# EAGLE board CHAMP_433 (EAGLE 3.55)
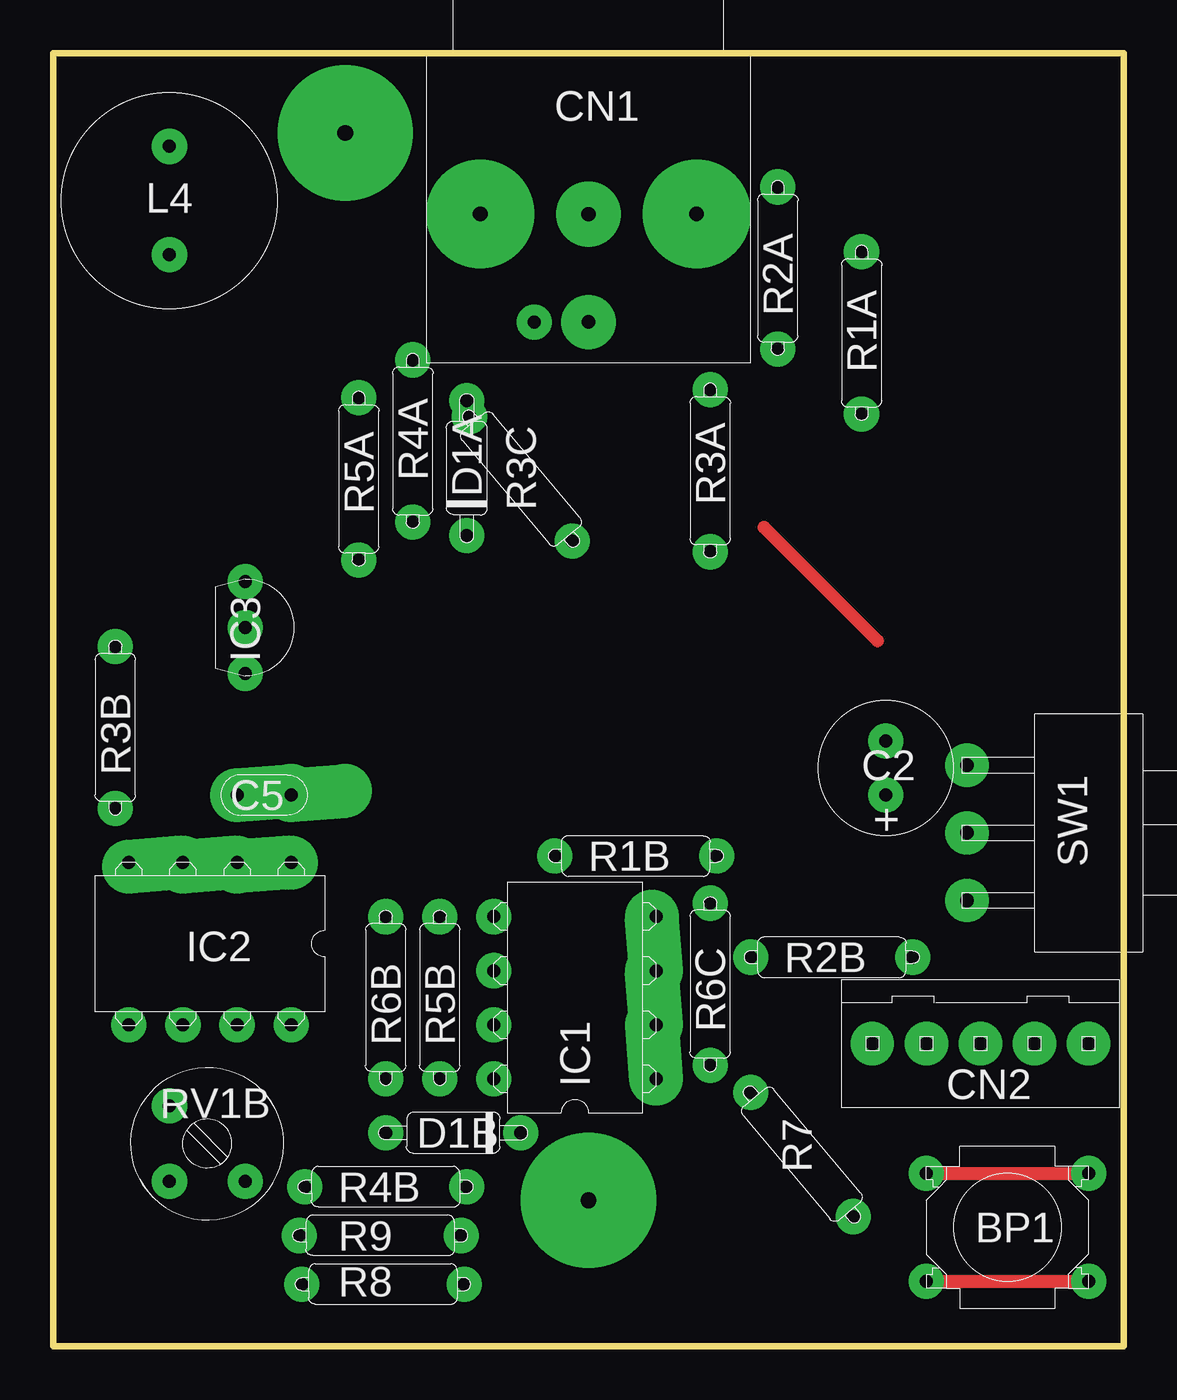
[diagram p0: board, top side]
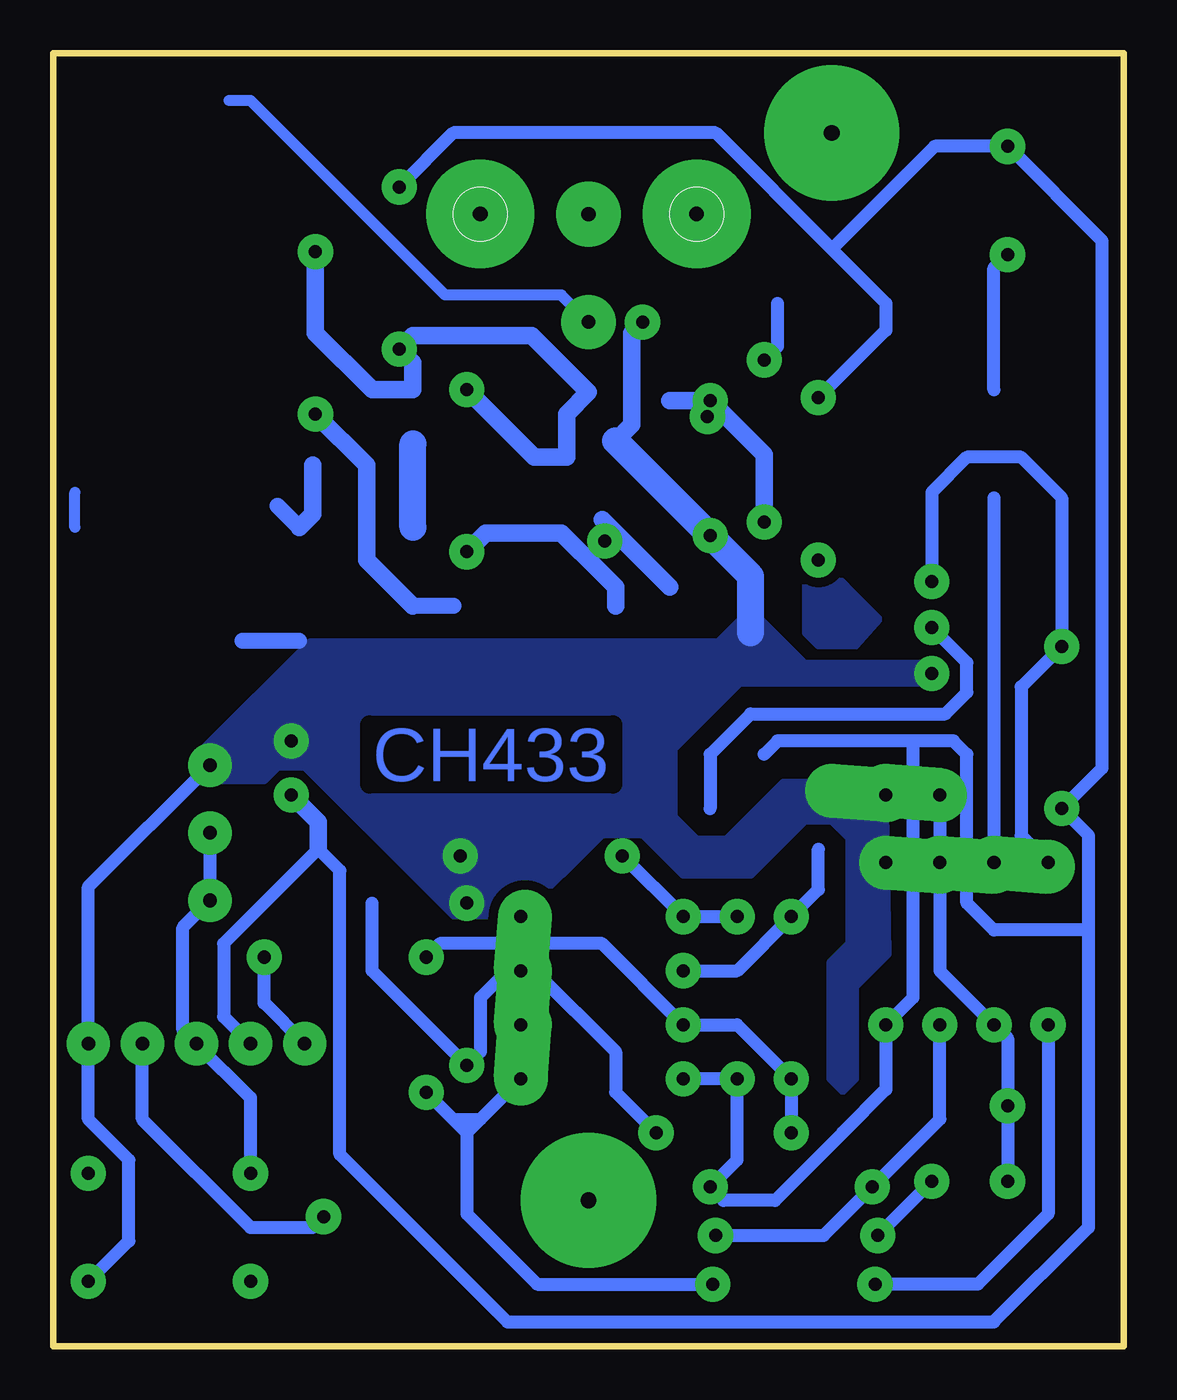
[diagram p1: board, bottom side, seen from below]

Size 50.29 x 60.77 mm. Coordinates in mm from the lower left corner, seen from the top.
Outline: 50.29,0 50.29,60.77 0,60.77 0,0 50.29,0
Copper layers used: COTE_COM, COTE_SOU
EXCL_SOU: area 24,26.4 to 35.4,29.2

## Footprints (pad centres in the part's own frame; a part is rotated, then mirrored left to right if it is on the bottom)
-MICRO = drill 0.612 pad 1.651 round:  -3.81,-2.54;  -3.81,2.54;  3.81,2.54;  3.81,-2.54
IM-6-0 = drill 0.612 pad 1.651 round:  -1.27,0;  1.27,0
2,5-1 = drill 0.612 pad 2.54 offset:  -1.27,0;  1.27,0
C-L = drill 0.691 pad 5.08 round:  5.08,0;  -5.08,0 | drill 0.637 pad 2.54 round:  0,5.08 | drill 0.612 pad 1.651 round:  2.54,5.08
14C05V = drill 0.637 pad 2.032 round:  -5.08,0;  -2.54,0;  0,0;  2.54,0;  5.08,0
6,3 = drill 0.612 pad 1.651 round:  3.175,0;  -3.175,0
-3,0MM = drill 0.744 pad 6.35 round:  0,0
L-08 = drill 0.612 pad 2.54 offset:  0,0;  2.54,0;  5.08,0 | drill 0.612 pad 1.651 round:  7.62,0;  7.62,7.62;  5.08,7.62;  2.54,7.62;  0,7.62
 = drill 0.612 pad 1.651 round:  2.159,0;  -2.159,0;  0,0
470MH = drill 0.612 pad 1.651 round:  -2.54,0;  2.54,0
10-7S = drill 0.612 pad 1.651 round:  -3.81,0;  3.81,0
ø0#R-1 = drill 0.612 pad 1.651 round:  -2.921,-2.413;  2.921,2.413
1T-45 = drill 0.612 pad 1.651 round:  -1.778,-1.778;  -1.778,1.778;  1.778,1.778
-GLIS = drill 0.637 pad 2.032 round:  0,3.175;  0,0;  0,-3.175

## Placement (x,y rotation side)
BP1  ON  [-MICRO]  44.83,5.59 0 top
BUZZER  PIEZO  [-PI13V]  6.1,42.42 270 top
C1A  104  [2,5-0]  13.21,11.3 90 top
C1B  104  [2,5-0]  36.58,23.37 180 top
C1C  104  [2,5-0]  34.04,20.83 180 top
C1D  104  [2,5-0]  33.4,43.69 270 top
C1E  104  [2,5-60]  24.51,43.69 90 top
C2  100æ  [IM-6-0]  39.12,27.18 90 top
C3  2p2  [2,5-0]  36.83,41.4 180 top
C4A  47p  [2,5-0]  24.51,37.59 90 top
C4B  47p  [2,5-0]  12.07,32.89 270 top
C5  10n  [2,5-1]  9.91,25.91 0 top
CN1  BNC  [C-L]  25.15,53.21 180 top
CN2  S +9- +G-  [14C05V]  43.56,14.22 0 top
CV1  1/6p  [VA-P34]  36.07,35.81 90 top
D1A  914  [6,3]  19.43,41.27 90 top
D1B  914  [6,3]  18.8,10.03 180 top
F1  FIXATION  [-3,0MM]  25.15,6.86 0 top
F2  FIXATION  [-3,0MM]  13.72,57.02 0 top
IC1  TLC272  [L-08]  28.32,12.57 90 top
IC1_SCH  TLC272  [082]  27.69,12.57 180 top
IC2  TLC555  [L-08]  11.18,22.73 180 top
IC2_SCH  TLC555  [5]  11.18,22.1 270 top
IC3  MC34064  []  9.02,33.78 270 top
L1  115mm  [433-A1]  45.09,48.89 0 top
L2  45nH  [433-13]  44.58,36.96 0 top
L3  4T/2,5  [4T-2,5]  27.43,40 0 top
L4  470mH  [470MH]  5.46,53.85 90 top
R1A  100K  [10-7S]  37.97,47.62 270 top
R1B  100K  [10-7S]  27.37,23.05 0 top
R2A  220R  [10-7S]  34.04,50.67 270 top
R2B  220R  [10-7S]  36.58,18.29 0 top
R3A  4K7  [10-7S]  30.86,41.15 270 top
R3B  4K7  [10-7S]  2.92,29.08 90 top
R3C  4K7  [ø0#R-1]  21.97,40.77 270 top
R4A  1K  [10-7S]  16.89,42.55 270 top
R4B  1K  [10-7S]  15.62,7.49 180 top
R5A  220K  [10-7S]  14.35,40.77 270 top
R5B  220K  [10-7S]  18.16,16.38 90 top
R6A  1M  [10]  14.35,28.45 270 top
R6B  1M  [10-7S]  15.62,16.38 90 top
R6C  1M  [10-7S]  30.86,17.02 90 top
R7  33K  [ø0#R-1]  35.18,9.02 90 top
R8  10K  [10-7S]  15.49,2.92 180 top
R9  33K  [10-7S]  15.37,5.21 180 top
RV1A  22K  [1T-00]  13.72,49.02 0 top
RV1B  22K  [1T-45]  7.24,9.52 90 top
RV1C  22K  [1T-00]  19.43,27.81 180 top
SW1  ON/OFF  [-GLIS]  42.93,24.13 0 top
T1A  BFR91  [BFR91I]  27.69,34.8 0 top
T1B  BFR91  [BFR91I]  17.53,35.69 0 top
U$6  [TRE-55]  13.72,57.02 0 top
U$24  [TRE-55]  25.15,6.86 0 top

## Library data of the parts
BP1 BUZZER D1A D1B F1 F2 IC3 L1-L4 R1A R1B R2A R2B R3A R3B R4A R4B R5A R5B R6A R6B R6C R8 R9 RV1A RV1B RV1C SW1 T1A T1B U$6 U$24 = EAGLE
C1A C1B C1C C1D C1E C2 C3 C4A C4B C5 CV1 = CONDO
CN1 = CONNEC
CN2 = CONN-HE
IC1 IC2 = INTEL
IC1_SCH IC2_SCH = SCHEMA
R3C R7 = RESISTAN

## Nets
0V: BP1. C1A. C1B. C1C. C1D. C1E. C2. C4B. C5. CN1. CN2. CV1. D1A. IC1. IC2. IC3. L2. R1B. R6C. RV1C. SW1. T1A. T1B.
0V_PILE: BP1. CN2. SW1.
3_+REPOS: BUZZER. IC2.
4V6_MINI: IC3. RV1C.
6-2_RC: C5. IC2. RV1B.
7: IC2. R4B. R9.
+9V: C1A. C1B. C2. CN2. IC1. IC2. L4. R2A. R3B. R4B. R5A. R5B. RV1A. RV1C.
+9V_FILT: C1D. C1E. L3. R1A. R2A. R3A.
+GALVANO: CN2. R7.
ANTENNE: CN1. L1.
B_T1A: C3. R1A. T1A.
B_T1B: C4A. R3C. T1B.
C_T1A: C4A. L3. R3A. T1A.
C_T1B: C4B. R5A. R6A. T1B.
E1+_TEMP: C1C. D1B. IC1. R6C.
E2+_+2V8: IC1. R1B. R5B.
E2-_IN: IC1. R6A. R6B.
F_MINI: R9. RV1B.
LC_433: C3. CV1. L2.
LCWý=1: BUZZER. L4.
MIL: L1. L2.
MIN: R4A. RV1A.
OSCILLO: CN2. R2B.
RST_555: IC2. IC3. R3B.
S1_+: IC1. R7. R8.
S2_+: D1B. IC1. R2B. R6B.
VCO_555: IC2. R8.
Z: D1A. R3C. R4A.

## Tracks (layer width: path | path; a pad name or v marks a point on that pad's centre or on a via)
0V
  COTE_COM 0.61: 41.02,3.05 BP1. | 33.4,38.48 38.73,33.15
  COTE_SOU 0.61: 42.93,27.3 48.64,21.59 CN2. 48.64,10.67 46.74,8.76 46.74,4.95 BP1.
  COTE_SOU 0.762: 38.73,33.15 41.4,33.15
  COTE_SOU 0.813: 23.88,42.55 23.11,43.31 23.11,47.62 CN1.
  COTE_SOU 1.27: 23.88,42.55 D1A. 17.53,36.2 17.53,33.53 | 33.4,38.48 33.4,42.42
  pour COTE_SOU (isolate 0.444, no thermals): 11.18,26.54 11.05,18.41 12.57,16.89 12.57,12.57 13.21,11.94 13.84,12.57 13.84,18.03 12.95,18.92 12.95,26.54
  pour COTE_SOU (isolate 0.444, no thermals): 11.18,26.54 16,26.54 18.67,23.88 20.07,23.88 21.08,24.89 21.08,28.07 18.03,31.12 8.89,31.12 8.38,31.62 8.89,32.13 14.99,32.13 17.53,34.67 19.05,33.15 38.23,33.15 43.31,28.07 43.31,26.54 40.39,26.54 39.75,27.18 38.48,27.18 31.5,20.19 28.32,20.19 24.51,24 22.61,24 20.7,22.1 17.53,22.1 14.99,24.64 13.72,24.64 12.83,23.75 11.18,23.75
0V_PILE
  COTE_COM 0.61: 41.02,8.13 48.64,8.13
  COTE_SOU 0.61: 42.93,24.13 SW1. 44.2,19.68 44.2,14.86 43.56,14.22 41.02,11.68 41.02,8.13
3_+REPOS
  COTE_SOU 0.61: 6.1,39.88 6.1,22.73
4V6_MINI
  COTE_SOU 0.61: 19.43,25.27 19.43,27.81 17.53,29.72 8.38,29.72 7.37,30.73 7.37,32.13 IC3.
6-2_RC
  COTE_SOU 0.61: 8.64,25.91 8.64,22.73 8.64,17.65 6.1,15.11 5.46,14.48 RV1B. 5.46,7.75
7
  COTE_SOU 0.61: 8.64,15.11 8.64,10.67 R4B. 14.1,5.21 19.18,5.21
+9V
  COTE_SOU 0.61: 13.72,51.56 11.18,49.02 11.18,47.75 14.35,44.58 | IC1. 18.16,12.57 18.16,8.76 19.43,7.49 18.8,6.86 16.38,6.86 13.21,10.03 11.18,12.06 IC2. 9.91,16.38 9.91,28.45 | 9.91,28.45 8,28.45 7.37,27.81 7.37,20.83 6.1,19.56 1.65,19.56 | 1.65,19.56 1.65,5.59 6.1,1.14 28.96,1.14 36.83,9.02 36.83,22.35 37.85,23.37 42.29,18.92 42.29,15.49 41.02,14.22 | 1.65,19.56 1.65,24 2.92,25.27 1.02,27.18 1.02,51.94 L4. 8.89,56.39 13.72,51.56 | 9.91,28.45 16.26,28.45 16.89,27.81 | 13.72,51.56 19.18,57.02 31.5,57.02 34.04,54.48
  COTE_SOU 0.813: 37.85,23.37 37.85,24.64 39.12,25.91
+9V_FILT
  COTE_SOU 0.813: 37.97,51.44 37.97,47.62 35.31,44.96 33.4,44.96 33.4,46.23 R2A. 33.4,47.5 27.81,47.5 25.15,44.83 26.16,43.81 26.16,41.78 27.69,41.78 30.86,44.96
+GALVANO
  COTE_SOU 0.61: 46.1,14.22 46.1,10.67 41.02,5.59 38.1,5.59 37.59,6.1
ANTENNE
  COTE_SOU 0.508: 25.15,48.13 26.42,49.4 31.88,49.4 41.02,58.55 42.04,58.55
B_T1A
  COTE_SOU 0.762: 31.5,34.8 33.4,34.8
  COTE_SOU 0.813: 33.4,34.8 35.56,36.96 35.56,41.4 R1A.
B_T1B
  COTE_SOU 0.813: 21.34,35.69 22.61,36.96 24.51,38.86
C_T1A
  COTE_SOU 0.813: 23.88,34.8 23.88,35.69 24.51,36.32 26.42,38.23 28.7,38.23 29.97,38.23 R3A.
C_T1B
  pour COTE_SOU (isolate 0.444, no thermals): 14.99,33.53 14.99,36.7 14.48,37.21 11.43,34.16 12.57,32.89 14.35,32.89
E1+_TEMP
  COTE_SOU 0.61: 35.31,20.83 35.31,17.65 30.86,13.21 30.23,13.84 30.23,15.75 30.23,16.38 28.96,17.65 28.32,17.65 27.69,17.65 23.88,13.84 23.88,11.94 D1B.
E2+_+2V8
  COTE_SOU 0.61: R5B. 20.7,20.19 23.56,23.05
E2-_IN
  COTE_SOU 0.61: 20.7,17.65 18.16,17.65 R6B. 14.35,21.46 14.35,23.37
F_MINI
  COTE_SOU 0.61: R9. 9.02,7.75
LC_433
  COTE_SOU 0.762: 38.73,38.48 39.75,39.5
  COTE_SOU 0.813: 38.1,41.4 38.1,39.12 38.73,38.48
LCWý=1
  COTE_SOU 0.61: 6.1,44.96 6.1,50.67 5.46,51.31
MIL
  COTE_SOU 0.508: 49.28,38.48 49.28,40.13
MIN
  COTE_SOU 0.61: 16.26,49.02 16.26,46.99 16.89,46.36
N$1  (via drill 0.66 pad 3.05)
  other vias: 25.15,53.21
OSCILLO
  COTE_SOU 0.61: 38.48,14.22 40.39,16.13 R2B.
RST_555
  COTE_SOU 0.61: 3.56,22.73 4.83,24 4.83,30.99 R3B. 2.92,39.88 4.83,41.78 7.37,41.78 9.02,40.13 9.02,35.94
S1_+
  COTE_SOU 0.61: 28.32,15.11 28.32,12.57 30.23,10.67 | 30.86,10.03 30.23,10.67 | R7. 31.5,10.67 | 31.5,10.67 30.86,10.03 | 19.3,2.92 27.56,2.92 30.86,6.22 30.86,10.03 | 31.5,10.67 30.23,10.67
S2_+
  COTE_SOU 0.61: 15.62,10.03 15.62,12.57 18.16,15.11 20.7,15.11 24.51,18.92 32.13,18.92 32.77,18.29
VCO_555
  COTE_SOU 0.61: 3.56,15.11 3.56,6.22 6.86,2.92 R8.
Z
  COTE_SOU 0.813: 21.34,44.45 19.43,44.45 16.89,41.91 R4A.

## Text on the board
COTE_SOU: CH433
